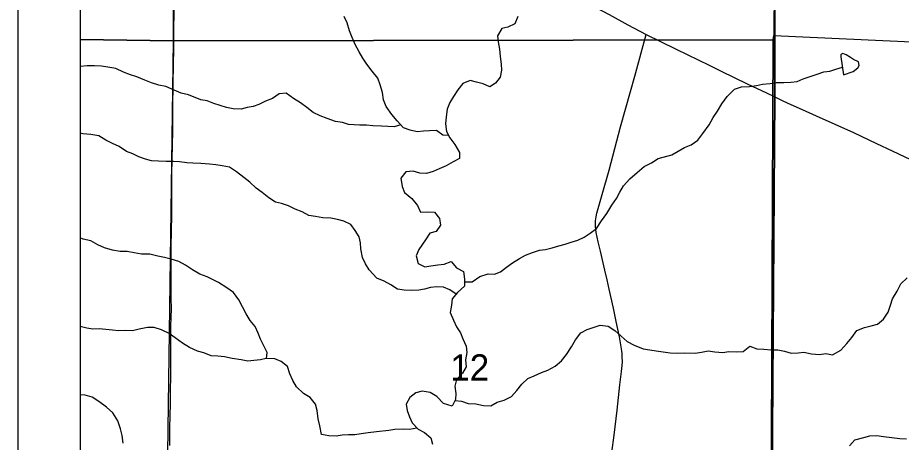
# Model space of a CAD drawing. Extents: x 0 to 34, y 0 to 22.
# Drawn here: x 2 to 3.412, y 15.21 to 15.888 of the extents above; entities that cross this region are included whole.
import ezdxf

# ---------------------------------------------------------------- set-up
doc = ezdxf.new("R2010")
doc.units = 0
for name, color, linetype in [('Default', 7, 'Continuous'), ('GM_X_Interstate_Route', 7, 'Continuous'), ('GM_X_Minor_Lake', 7, 'Continuous'), ('GM_X_Minor_River', 7, 'Continuous'), ('GM_X_Section', 7, 'Continuous'), ('GM_X_Section_Text', 7, 'Continuous'), ('GM_X_Township_Road', 7, 'Continuous'), ('SH_Cut_Line', 7, 'Continuous'), ('SH_Data', 7, 'Continuous')]:
    doc.layers.add(name, color=color, linetype=linetype)

msp = doc.modelspace()

# ---------------------------------------------------------------- linework, layer by layer
at = {"layer": 'Default'}
for points in [[(2.1, 16.8795), (2.1, 15.8527), (2.249, 15.8507), (2.253, 16.8782)], [(2.1, 15.8527), (2.1, 14.8453), (2.2353, 14.8433), (2.249, 15.8507)]]:
    msp.add_lwpolyline(points, close=True, dxfattribs=at)
at = {"layer": 'GM_X_Interstate_Route'}
msp.add_lwpolyline([(2.1, 16.8784), (2.1, 14.1), (3.2011, 14.1), (3.2037, 14.7782), (3.2041, 14.9016), (3.2042, 14.9221), (3.2098, 15.7617), (3.2111, 16.7578), (3.2115, 16.8719), (3.0939, 16.8719), (2.6014, 16.878)], close=True, dxfattribs=at)
msp.add_lwpolyline([(4.6269, 16.8701), (3.6554, 16.8713), (3.6203, 16.8714), (3.2115, 16.8719), (3.2111, 16.7578), (3.2098, 15.7617), (3.2042, 14.9221), (3.2041, 14.9016), (3.2037, 14.7782), (3.2011, 14.1), (8.2568, 14.1)], dxfattribs=at)
at = {"layer": 'GM_X_Minor_Lake'}
for points in [[(3.3198, 15.7967), (3.3353, 15.8018), (3.3426, 15.8078), (3.3449, 15.8112), (3.3438, 15.8173), (3.3355, 15.8212), (3.331, 15.8239), (3.3238, 15.8285), (3.3185, 15.8308), (3.3155, 15.8289), (3.3155, 15.8252)], [(3.3155, 15.8252), (3.3198, 15.7967)]]:
    msp.add_lwpolyline(points, dxfattribs=at)
at = {"layer": 'GM_X_Minor_River'}
for points in [[(2.6889, 15.6996), (2.6794, 15.7), (2.6692, 15.7074), (2.6583, 15.7071), (2.6484, 15.7064), (2.6382, 15.7054), (2.6272, 15.7081), (2.6167, 15.7117), (2.6065, 15.7231), (2.5979, 15.7331), (2.5889, 15.7457), (2.5848, 15.7564), (2.5831, 15.7681), (2.5794, 15.7803), (2.5753, 15.7914), (2.5667, 15.8025), (2.5581, 15.8135), (2.5517, 15.8231), (2.5457, 15.8334), (2.5394, 15.8448), (2.5346, 15.8559), (2.5305, 15.8666), (2.5264, 15.8795), (2.522, 15.8898)], [(2.7995, 15.8897), (2.7945, 15.878), (2.7831, 15.8724), (2.7736, 15.8706), (2.7667, 15.8589), (2.7681, 15.8491), (2.7699, 15.8373), (2.7713, 15.8255), (2.7724, 15.8134), (2.7731, 15.8039), (2.7711, 15.7929), (2.7638, 15.7831), (2.7543, 15.7775), (2.7441, 15.7821), (2.7335, 15.7849), (2.7229, 15.7873), (2.7115, 15.7825), (2.7035, 15.7723), (2.6966, 15.7621), (2.6908, 15.7523), (2.6862, 15.7417), (2.6846, 15.7292), (2.6837, 15.7182), (2.6855, 15.7061), (2.6907, 15.6961), (2.6986, 15.6851), (2.7061, 15.6725), (2.706, 15.663), (2.6961, 15.6574), (2.6847, 15.6514), (2.6737, 15.6466), (2.6638, 15.6421), (2.6531, 15.6388), (2.6425, 15.6397), (2.632, 15.6425)], [(2.6123, 15.7166), (2.6015, 15.7133), (2.5913, 15.7142), (2.5815, 15.7143), (2.5675, 15.7148), (2.5572, 15.716), (2.547, 15.7161), (2.5289, 15.7174), (2.519, 15.7202), (2.5077, 15.7222), (2.4945, 15.7265), (2.4835, 15.7312), (2.4722, 15.7366), (2.4621, 15.7443), (2.4519, 15.7516), (2.4406, 15.7589), (2.4289, 15.7674), (2.4179, 15.766), (2.4073, 15.7585), (2.3959, 15.7544), (2.3856, 15.7492), (2.3761, 15.7459), (2.3666, 15.7444), (2.3572, 15.7419), (2.3443, 15.7424), (2.3337, 15.7444), (2.3133, 15.7507), (2.3027, 15.7549), (2.2925, 15.7566), (2.2729, 15.7643), (2.2612, 15.7671), (2.2499, 15.7718), (2.2367, 15.7776), (2.2257, 15.78), (2.2136, 15.7839), (2.2034, 15.7878), (2.1902, 15.7932), (2.1804, 15.7967), (2.1691, 15.801), (2.157, 15.8068), (2.1442, 15.8085), (2.1339, 15.8101), (2.1226, 15.8109), (2.1109, 15.8111), (2.1, 15.81)], [(2.7139, 15.4658), (2.7263, 15.4662), (2.7388, 15.4745), (2.7518, 15.4785), (2.762, 15.4784), (2.7715, 15.4817), (2.7814, 15.4896), (2.7909, 15.4963), (2.8019, 15.5034), (2.8115, 15.5083), (2.8228, 15.5127), (2.8339, 15.5164), (2.8437, 15.5178), (2.8543, 15.5204), (2.8646, 15.5237), (2.8748, 15.5263), (2.8847, 15.5292), (2.895, 15.5325), (2.9052, 15.5373), (2.9147, 15.5437), (2.925, 15.5512), (2.9331, 15.5633), (2.9415, 15.5749), (2.9496, 15.5885), (2.9569, 15.5991), (2.9623, 15.6093), (2.9684, 15.6191), (2.9783, 15.6304), (2.9898, 15.6405), (3.0012, 15.6499), (3.013, 15.6562), (3.0233, 15.6629), (3.0453, 15.6688), (3.0556, 15.6748), (3.0658, 15.6804), (3.0765, 15.6848), (3.0868, 15.6923), (3.0948, 15.7028), (3.1048, 15.7168), (3.1113, 15.7285), (3.1182, 15.7383), (3.1255, 15.75), (3.1339, 15.7617), (3.1458, 15.7737), (3.1568, 15.7774), (3.1697, 15.778), (3.1807, 15.7794), (3.1901, 15.7816), (3.2026, 15.7826), (3.2121, 15.7844), (3.2242, 15.7843), (3.2356, 15.7849), (3.2455, 15.786), (3.2553, 15.7901), (3.2664, 15.7938), (3.2778, 15.7978), (3.2884, 15.8011), (3.2979, 15.8026), (3.3077, 15.8055), (3.318, 15.8087)], [(2.7005, 15.4463), (2.6906, 15.4533), (2.6804, 15.4576), (2.6698, 15.4581), (2.6599, 15.457), (2.6504, 15.4541), (2.641, 15.4526), (2.63, 15.452), (2.6175, 15.4529), (2.6069, 15.4545), (2.5964, 15.4614), (2.5858, 15.4672), (2.5737, 15.4719), (2.5617, 15.4853), (2.5557, 15.4948), (2.5509, 15.5047), (2.5484, 15.5188), (2.5477, 15.5283), (2.5455, 15.5378), (2.5392, 15.5481), (2.5324, 15.5577), (2.5211, 15.5627), (2.5113, 15.5655), (2.5003, 15.5675), (2.4878, 15.568), (2.4761, 15.5704), (2.4655, 15.572), (2.4546, 15.5778), (2.4436, 15.5821), (2.4327, 15.5875), (2.4218, 15.591), (2.4119, 15.5934), (2.4014, 15.6003), (2.3909, 15.6084), (2.3811, 15.6153), (2.3709, 15.6249), (2.3612, 15.6326), (2.3499, 15.6414), (2.3386, 15.6491), (2.3268, 15.6511), (2.3166, 15.6527), (2.3064, 15.6536), (2.2928, 15.6549), (2.2799, 15.6554), (2.2701, 15.6558), (2.2587, 15.6575), (2.2489, 15.6579), (2.2375, 15.658), (2.2251, 15.6589), (2.2141, 15.659), (2.2043, 15.6618), (2.1937, 15.6653), (2.1839, 15.6703), (2.1737, 15.6742), (2.162, 15.6823), (2.1518, 15.6866), (2.1409, 15.692), (2.1296, 15.6993), (2.1171, 15.7013), (2.1043, 15.7022), (2.1, 15.7036)], [(2.632, 15.6425), (2.6202, 15.6414), (2.6122, 15.6316), (2.6143, 15.6183), (2.6184, 15.6084), (2.6297, 15.5988), (2.6387, 15.5881), (2.6439, 15.5771), (2.6557, 15.5777), (2.6659, 15.5772), (2.6741, 15.5669), (2.6755, 15.5567), (2.669, 15.5465), (2.6584, 15.5435), (2.6515, 15.533), (2.6411, 15.5175), (2.6369, 15.5073), (2.6402, 15.4955), (2.6507, 15.4901), (2.6602, 15.4915), (2.6716, 15.4933), (2.6818, 15.4944), (2.6928, 15.4984), (2.7011, 15.4885), (2.7124, 15.4823), (2.7138, 15.4705), (2.7141, 15.4588), (2.7027, 15.449), (2.6946, 15.4388), (2.6934, 15.4286), (2.6914, 15.4169), (2.6966, 15.4047), (2.7014, 15.3944), (2.7078, 15.3844), (2.7115, 15.3749), (2.7167, 15.3635), (2.7177, 15.3532), (2.7158, 15.3415), (2.7168, 15.3301), (2.711, 15.3203), (2.7011, 15.3101), (2.6987, 15.2992), (2.7002, 15.2878), (2.6997, 15.2779), (2.6943, 15.2677), (2.6803, 15.2716), (2.6698, 15.2831), (2.6593, 15.2893), (2.6464, 15.2913), (2.6362, 15.2888), (2.6266, 15.2813), (2.6209, 15.2707), (2.6227, 15.2604), (2.626, 15.2505), (2.6305, 15.241), (2.6398, 15.2307), (2.6504, 15.2253), (2.6602, 15.2168), (2.6631, 15.2069)], [(2.3978, 15.3434), (2.3989, 15.3533), (2.3926, 15.3647), (2.3881, 15.3743), (2.3844, 15.3838), (2.3796, 15.3945), (2.3717, 15.404), (2.3654, 15.4147), (2.3594, 15.4262), (2.3534, 15.4372), (2.3448, 15.4487), (2.3343, 15.4564), (2.3207, 15.4649), (2.3026, 15.4738), (2.2913, 15.478), (2.2792, 15.485), (2.268, 15.4927), (2.2574, 15.4985), (2.2453, 15.5024), (2.2344, 15.5048), (2.2238, 15.5072), (2.2113, 15.5099), (2.1981, 15.5101), (2.186, 15.5121), (2.175, 15.5145), (2.1636, 15.5146), (2.1515, 15.5166), (2.1387, 15.5201), (2.1281, 15.5252), (2.1168, 15.5313), (2.1047, 15.5341), (2.1, 15.5361)], [(2.6991, 15.2767), (2.7091, 15.2755), (2.7197, 15.2716), (2.7322, 15.2711), (2.7443, 15.2684), (2.756, 15.2682), (2.7663, 15.2738), (2.7777, 15.2771), (2.7891, 15.2827), (2.7975, 15.2925), (2.8055, 15.3027), (2.8151, 15.3117), (2.8254, 15.3161), (2.8371, 15.3213), (2.8474, 15.3247), (2.8592, 15.3314), (2.8691, 15.3396), (2.8768, 15.3502), (2.8848, 15.3622), (2.8913, 15.3732), (2.8998, 15.3845), (2.91, 15.3901), (2.9214, 15.3934), (2.9309, 15.3967), (2.9434, 15.3954), (2.9543, 15.3885), (2.9645, 15.3793), (2.9742, 15.3705), (2.9852, 15.3651), (2.9995, 15.3592), (3.0101, 15.3576), (3.0203, 15.3556), (3.0317, 15.354), (3.0426, 15.3527), (3.0547, 15.3522), (3.0661, 15.3525), (3.0828, 15.352), (3.093, 15.3538), (3.1036, 15.3556), (3.1142, 15.3543), (3.1267, 15.3534), (3.1366, 15.3549), (3.1487, 15.354), (3.1593, 15.3546), (3.1703, 15.3633), (3.1813, 15.359), (3.1926, 15.3585), (3.2036, 15.3576), (3.215, 15.3575), (3.2255, 15.3555), (3.2361, 15.352), (3.2471, 15.3526), (3.2566, 15.3537), (3.2687, 15.3509), (3.2812, 15.35), (3.2914, 15.3518), (3.302, 15.3495), (3.3157, 15.3569), (3.3252, 15.3674), (3.3329, 15.3772), (3.3413, 15.3885), (3.3535, 15.3933), (3.3637, 15.3955), (3.3743, 15.3985), (3.3839, 15.4063), (3.3912, 15.4176), (3.3947, 15.4286), (3.3982, 15.4388), (3.4055, 15.4513), (3.4112, 15.4626), (3.4215, 15.4724)], [(2.6381, 15.2326), (2.6262, 15.2304), (2.616, 15.2309), (2.6027, 15.2303), (2.5929, 15.2285), (2.5732, 15.2264), (2.5599, 15.225), (2.5489, 15.2232), (2.539, 15.2218), (2.5288, 15.2219), (2.5186, 15.2212), (2.5091, 15.2194), (2.4974, 15.2199), (2.4853, 15.2223), (2.4831, 15.236), (2.4802, 15.2474), (2.4784, 15.2603), (2.4758, 15.2706), (2.4676, 15.2813), (2.4567, 15.2879), (2.4458, 15.2986), (2.4398, 15.3085), (2.435, 15.3192), (2.4313, 15.3306), (2.4211, 15.3387), (2.411, 15.3429), (2.3973, 15.3434), (2.3878, 15.3416), (2.3776, 15.3402), (2.3678, 15.3392), (2.3572, 15.3412), (2.3428, 15.3436), (2.3303, 15.346), (2.3197, 15.3472), (2.3091, 15.3477), (2.2974, 15.3524), (2.2876, 15.3551), (2.2744, 15.3613), (2.2635, 15.3683), (2.2518, 15.3764), (2.242, 15.3833), (2.23, 15.3895), (2.2179, 15.393), (2.2073, 15.3931), (2.194, 15.3902), (2.1834, 15.388), (2.172, 15.3885), (2.1614, 15.3879), (2.1516, 15.3887), (2.141, 15.39), (2.13, 15.3908), (2.1202, 15.3905), (2.1103, 15.3918), (2.1, 15.3946)], [(2.1686, 15.2083), (2.1668, 15.2208), (2.1643, 15.2315), (2.1598, 15.2441), (2.152, 15.2567), (2.1422, 15.2659), (2.1298, 15.2751), (2.1189, 15.2816), (2.1079, 15.2848), (2.1, 15.2854)], [(3.3295, 15.2039), (3.3379, 15.2136), (3.3524, 15.2173), (3.3618, 15.2202), (3.3728, 15.2205), (3.3834, 15.2193), (3.397, 15.2172), (3.4095, 15.216), (3.4205, 15.2155)]]:
    msp.add_lwpolyline(points, dxfattribs=at)
at = {"layer": 'GM_X_Section'}
for points in [[(3.1023, 16.8785), (3.2153, 16.8759), (3.2082, 15.8593), (3.2075, 15.8525), (2.249, 15.8507), (2.253, 16.8782)], [(4.2148, 16.747), (4.2083, 16.8683), (4.1045, 16.8706), (3.2153, 16.8759), (3.2082, 15.8593), (4.2651, 15.8107), (4.2549, 16), (4.1282, 16), (4.1282, 16.747)], [(3.2082, 15.8593), (4.2651, 15.8107), (4.2381, 14.8083), (3.2026, 14.8175), (3.2029, 14.8323), (3.2075, 15.8525)], [(3.2075, 15.8525), (3.2029, 14.8323), (2.2353, 14.8433), (2.249, 15.8507)]]:
    msp.add_lwpolyline(points, close=True, dxfattribs=at)
at = {"layer": 'GM_X_Township_Road'}
msp.add_line((3.21, 15.7611), (3.2209, 15.756), dxfattribs=at)
for points in [[(2.7294, 15.9713), (2.7313, 15.9707), (2.771, 15.9627), (2.7925, 15.9593), (2.814, 15.9558), (2.8201, 15.9546), (2.8261, 15.953), (2.832, 15.951), (2.8405, 15.9473), (2.8599, 15.9374), (2.8818, 15.9257), (2.9011, 15.9157), (2.9203, 15.9057), (2.9341, 15.8985), (2.945, 15.8926), (2.9751, 15.8764), (3.0045, 15.8611)], [(2.243, 15.2047), (2.2434, 15.2336), (2.2441, 15.2711), (2.2441, 15.2867), (2.2446, 15.3208), (2.2447, 15.3457), (2.2448, 15.3705), (2.2446, 15.3829), (2.2448, 15.3953), (2.2456, 15.4233), (2.2454, 15.4392), (2.2452, 15.4706), (2.2452, 15.4916), (2.2452, 15.5226), (2.2461, 15.5723), (2.2462, 15.5971), (2.2463, 15.6095), (2.2464, 15.6375), (2.2469, 15.6621), (2.2475, 15.6848), (2.2479, 15.706), (2.2479, 15.7217), (2.2482, 15.7434), (2.2487, 15.7837), (2.249, 15.8114), (2.2494, 15.8394), (2.2495, 15.8643), (2.2499, 15.9016)], [(2.9497, 15.1935), (2.953, 15.2213), (2.9579, 15.2613), (2.9625, 15.3014), (2.9649, 15.323), (2.9659, 15.3322), (2.9663, 15.3385), (2.9661, 15.3461), (2.9658, 15.3508), (2.9655, 15.356), (2.9646, 15.3624), (2.9615, 15.3784), (2.9566, 15.4028), (2.9521, 15.424), (2.9453, 15.4543), (2.9418, 15.4694), (2.9383, 15.4845), (2.9313, 15.5147), (2.9278, 15.5298), (2.9247, 15.545), (2.9235, 15.5543), (2.9232, 15.5605), (2.9234, 15.5636), (2.9243, 15.5697), (2.9257, 15.5757), (2.9343, 15.6056), (2.9453, 15.6444), (2.9636, 15.7134), (2.9794, 15.7699), (2.986, 15.7942), (3.0045, 15.8611)], [(3.0045, 15.8611), (3.0273, 15.8496), (3.0522, 15.8375), (3.1049, 15.8119), (3.1244, 15.8025), (3.166, 15.7823), (3.1965, 15.7675), (3.21, 15.7611)], [(3.2209, 15.756), (3.2308, 15.7514), (3.2535, 15.7413), (3.2762, 15.7312), (3.3357, 15.7043), (3.3722, 15.687), (3.3975, 15.6751), (3.4369, 15.6564)]]:
    msp.add_lwpolyline(points, dxfattribs=at)
at = {"layer": 'SH_Cut_Line'}
msp.add_lwpolyline([(2.1, 20.9), (2.1, 14.1), (8.2568, 14.1)], dxfattribs=at)
at = {"layer": 'SH_Data'}
for p, q in [((2, 21), (2, 14)), ((2.1, 20.9), (2.1, 14.1))]:
    msp.add_line(p, q, dxfattribs=at)

# ---------------------------------------------------------------- texts
at = {"layer": 'GM_X_Section_Text'}
msp.add_text('12', height=0.04186, rotation=0, dxfattribs=at).set_placement((2.6913, 15.3084))

doc.saveas('drawing.dxf')
